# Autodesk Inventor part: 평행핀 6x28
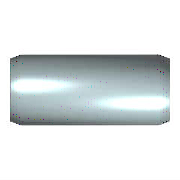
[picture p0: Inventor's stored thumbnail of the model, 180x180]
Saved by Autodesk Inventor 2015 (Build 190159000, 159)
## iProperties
Created: 2012-02
Part Number: 평행핀 6x28
Material: 스테인리스강
Description: 평행 핀
Document SubType Name: Modeling
Standard: KS B 1320
Designer: mduedu
Standards Organization: KS
Language: ko-KR
Size Designation: B 6 x  28
Categories: <MemberInstance><Categories><Category DisplayName="조임쇠" InternalName="e4da775c-781d-43d5-af7c-5136215cf5a6" Mnemonic="FSTN"><Category DisplayName="핀" InternalNa
Density: 1 g/cm^3
Appearance: 주황색
IsCustomPart: 1
Author: mduedu
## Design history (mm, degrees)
sketch "스케치"
  geometry: C1 r 3 at (0, 0); 1 further point
  constraints: 1 centre point, 1 coincident
  dimensions: "d1" = 6 diameter of C1 (= NND)
extrude "본체" new body sketch "스케치" distance "d2" = 28 (= NLG); taper "d3" = 0 deg
chamfer "스케치2" distance "d8" = 1.2 (= PHH); stored, may be unused: angle "d9" = 15 deg (= FAWI), second distance "d12" = 1.2 (= PHH)
node "작업 평면1"
body "Solid1"
chamfer "모따기1" distance "d4" = 1.2 (= PHH); stored, may be unused: angle "d5" = 15 deg (= FAWI), second distance "d11" = 1.2 (= PHH)
other parameters: "NND" = 6 [user parameter; used in 1 equation term], "NLG" = 28 [user parameter; used in 1 equation term], "PHH" = 1.2 [user parameter; used in 4 equation terms], "FAWI" = 15 deg [user parameter; used in 2 equation terms], "d13" = 0, "d15" = 0, "d16" = 0, "KAH" = 0.8 [user parameter]
